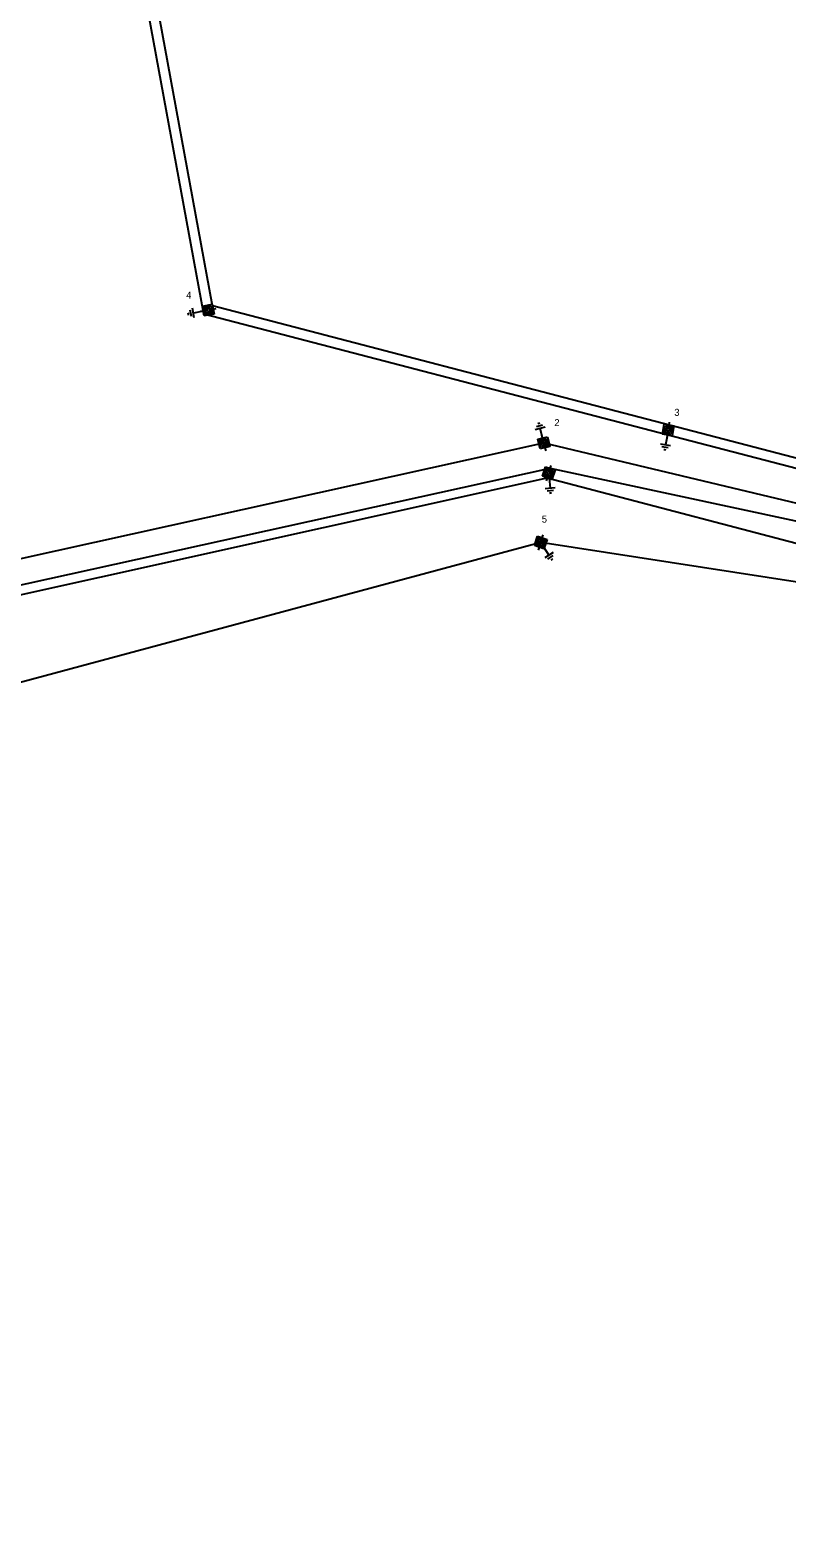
# Model space of a CAD drawing. Extents: x -763667 to -762498, y -1153000 to -1152000.
# Drawn here: x -762873.3 to -762686.7, y -1153000 to -1152628.2 of the extents above; entities that cross this region are included whole.
import ezdxf

# ---------------------------------------------------------------- set-up
doc = ezdxf.new("R2010")
doc.units = 0
for name, color, linetype in [('Vrstva 1', 7, 'Continuous'), ('Vrstva 13', 7, 'Continuous'), ('Vrstva 14', 7, 'Continuous'), ('Vrstva 15', 7, 'Continuous')]:
    doc.layers.add(name, color=color, linetype=linetype)

msp = doc.modelspace()

# ---------------------------------------------------------------- linework, layer by layer
at = {"layer": 'Vrstva 1'}
for points in [[(-762611.69, -1152755.21), (-762716.24, -1152727.97), (-762830.46, -1152698.21), (-762852.05, -1152580.65), (-762874.15, -1152462.04), (-762921.99, -1152375.79), (-763004.89, -1152226.38), (-763072.5, -1152104.65), (-763130.71, -1152000)], [(-762610.93, -1152752.83), (-762715.6, -1152725.55), (-762828.29, -1152696.16), (-762849.59, -1152580.19), (-762871.62, -1152461.96)], [(-763515.95, -1153000), (-763408.81, -1152935.67), (-763253.73, -1152842.91), (-763084.04, -1152804.87), (-762913.18, -1152766.77), (-762746.61, -1152729.95), (-762623.2, -1152759.36)], [(-763503.85, -1153000), (-763406.01, -1152941.37), (-763250.71, -1152848.67), (-763082.9, -1152811.11), (-762911.77, -1152772.97), (-762745.04, -1152736.18), (-762624.04, -1152762.13)], [(-763499.11, -1153000), (-763404.8, -1152943.47), (-763250.15, -1152850.99), (-763082.25, -1152813.42), (-762911.4, -1152775.32), (-762745.76, -1152738.55), (-762671.17, -1152758.11)], [(-762675.53, -1152765.62), (-762747.37, -1152754.51), (-762877.29, -1152789.43), (-763003.47, -1152823.28), (-763146.35, -1152861.67), (-763295.27, -1152929.58), (-763425.09, -1152988.74), (-763449.87, -1153000)]]:
    msp.add_lwpolyline(points, dxfattribs=at)
at = {"layer": 'Vrstva 13'}
for points in [[(-762830.815, -1152696.229), (-762828.403, -1152695.76)], [(-762828.403, -1152695.76), (-762827.934, -1152698.172)], [(-762830.581, -1152697.435), (-762831.315, -1152697.578)], [(-762830.346, -1152698.641), (-762830.815, -1152696.229)], [(-762830.474, -1152696.476), (-762828.665, -1152696.124)], [(-762830.122, -1152698.284), (-762830.474, -1152696.476)], [(-762827.934, -1152698.172), (-762830.346, -1152698.641)], [(-762828.314, -1152697.933), (-762830.122, -1152698.284)], [(-762830.095, -1152696.715), (-762828.889, -1152696.48)], [(-762829.861, -1152697.921), (-762830.095, -1152696.715)], [(-762828.654, -1152697.686), (-762829.861, -1152697.921)], [(-762829.697, -1152696.95), (-762829.094, -1152696.833)], [(-762829.58, -1152697.553), (-762829.697, -1152696.95)], [(-762828.977, -1152697.436), (-762829.58, -1152697.553)], [(-762829.094, -1152696.833), (-762828.977, -1152697.436)], [(-762828.889, -1152696.48), (-762828.654, -1152697.686)], [(-762828.665, -1152696.124), (-762828.314, -1152697.933)], [(-762828.169, -1152696.966), (-762827.434, -1152696.823)], [(-762717.344, -1152727.761), (-762716.917, -1152725.341)], [(-762716.917, -1152725.341), (-762714.498, -1152725.768)], [(-762715.708, -1152725.555), (-762715.578, -1152724.818)], [(-762748.098, -1152729.059), (-762745.715, -1152728.465)], [(-762747.504, -1152731.443), (-762748.098, -1152729.059)], [(-762747.721, -1152729.302), (-762745.934, -1152728.856)], [(-762747.275, -1152731.09), (-762747.721, -1152729.302)], [(-762747.354, -1152729.507), (-762746.162, -1152729.209)], [(-762746.906, -1152728.762), (-762747.087, -1152728.036)], [(-762746.162, -1152729.209), (-762745.865, -1152730.402)], [(-762745.934, -1152728.856), (-762745.488, -1152730.644)], [(-762745.715, -1152728.465), (-762745.12, -1152730.849)], [(-762714.925, -1152728.188), (-762717.344, -1152727.761)], [(-762716.992, -1152727.531), (-762716.672, -1152725.716)], [(-762715.177, -1152727.851), (-762716.992, -1152727.531)], [(-762716.672, -1152725.716), (-762714.857, -1152726.036)], [(-762716.633, -1152727.263), (-762716.419, -1152726.053)], [(-762715.423, -1152727.476), (-762716.633, -1152727.263)], [(-762716.419, -1152726.053), (-762715.21, -1152726.266)], [(-762716.27, -1152726.976), (-762716.163, -1152726.371)], [(-762715.665, -1152727.082), (-762716.27, -1152726.976)], [(-762716.134, -1152727.974), (-762716.264, -1152728.711)], [(-762716.163, -1152726.371), (-762715.559, -1152726.478)], [(-762715.559, -1152726.478), (-762715.665, -1152727.082)], [(-762715.21, -1152726.266), (-762715.423, -1152727.476)], [(-762714.857, -1152726.036), (-762715.177, -1152727.851)], [(-762714.498, -1152725.768), (-762714.925, -1152728.188)], [(-762745.12, -1152730.849), (-762747.504, -1152731.443)], [(-762747.056, -1152730.699), (-762747.354, -1152729.507)], [(-762745.488, -1152730.644), (-762747.275, -1152731.09)], [(-762745.865, -1152730.402), (-762747.056, -1152730.699)], [(-762746.991, -1152729.693), (-762746.395, -1152729.545)], [(-762746.842, -1152730.289), (-762746.991, -1152729.693)], [(-762746.246, -1152730.141), (-762746.842, -1152730.289)], [(-762746.395, -1152729.545), (-762746.246, -1152730.141)], [(-762746.312, -1152731.146), (-762746.131, -1152731.872)], [(-762746.939, -1152738.193), (-762746.18, -1152735.856)], [(-762746.558, -1152738.014), (-762745.988, -1152736.262)], [(-762746.18, -1152735.856), (-762743.843, -1152736.616)], [(-762746.165, -1152737.799), (-762745.785, -1152736.63)], [(-762745.988, -1152736.262), (-762744.236, -1152736.831)], [(-762745.785, -1152736.63), (-762744.617, -1152737.01)], [(-762745.011, -1152736.236), (-762744.78, -1152735.525)], [(-762744.236, -1152736.831), (-762744.806, -1152738.584)], [(-762743.843, -1152736.616), (-762744.603, -1152738.952)], [(-762744.603, -1152738.952), (-762746.939, -1152738.193)], [(-762744.806, -1152738.584), (-762746.558, -1152738.014)], [(-762744.997, -1152738.179), (-762746.165, -1152737.799)], [(-762745.771, -1152738.573), (-762746.002, -1152739.284)], [(-762745.766, -1152737.565), (-762745.576, -1152736.981)], [(-762745.182, -1152737.755), (-762745.766, -1152737.565)], [(-762745.576, -1152736.981), (-762744.992, -1152737.171)], [(-762744.992, -1152737.171), (-762745.182, -1152737.755)], [(-762744.617, -1152737.01), (-762744.997, -1152738.179)], [(-762748.933, -1152755.276), (-762748.133, -1152752.953)], [(-762746.61, -1152756.076), (-762748.933, -1152755.276)], [(-762748.548, -1152755.104), (-762747.949, -1152753.362)], [(-762746.806, -1152755.704), (-762748.548, -1152755.104)], [(-762748.152, -1152754.895), (-762747.752, -1152753.733)], [(-762746.991, -1152755.295), (-762748.152, -1152754.895)], [(-762748.133, -1152752.953), (-762745.81, -1152753.753)], [(-762747.949, -1152753.362), (-762746.207, -1152753.961)], [(-762747.752, -1152753.733), (-762746.591, -1152754.133)], [(-762747.749, -1152754.668), (-762747.549, -1152754.088)], [(-762747.168, -1152754.868), (-762747.749, -1152754.668)], [(-762747.549, -1152754.088), (-762746.968, -1152754.288)], [(-762746.968, -1152754.288), (-762747.168, -1152754.868)], [(-762746.591, -1152754.133), (-762746.991, -1152755.295)], [(-762746.971, -1152753.353), (-762746.728, -1152752.645)], [(-762746.207, -1152753.961), (-762746.806, -1152755.704)], [(-762745.81, -1152753.753), (-762746.61, -1152756.076)], [(-762747.771, -1152755.676), (-762748.015, -1152756.383)]]:
    msp.add_lwpolyline(points, dxfattribs=at)
at = {"layer": 'Vrstva 15'}
for points in [[(-762834.275, -1152698.157), (-762834.324, -1152697.905)], [(-762834.224, -1152698.418), (-762834.275, -1152698.157)], [(-762833.51, -1152698.79), (-762833.811, -1152697.244)], [(-762832.81, -1152699.145), (-762833.287, -1152696.691)], [(-762830.594, -1152697.441), (-762833.048, -1152697.918)], [(-762748.415, -1152725.899), (-762746.887, -1152725.518)], [(-762748.08, -1152725.167), (-762747.822, -1152725.102)], [(-762747.822, -1152725.102), (-762747.574, -1152725.04)], [(-762748.733, -1152726.618), (-762746.307, -1152726.013)], [(-762746.915, -1152728.741), (-762747.52, -1152726.315)], [(-762716.133, -1152727.989), (-762716.567, -1152730.451)], [(-762715.336, -1152730.668), (-762717.798, -1152730.234)], [(-762715.918, -1152731.195), (-762717.47, -1152730.921)], [(-762716.784, -1152731.682), (-762717.036, -1152731.637)], [(-762716.522, -1152731.728), (-762716.784, -1152731.682)], [(-762745.277, -1152738.642), (-762745.059, -1152741.133)], [(-762743.814, -1152741.024), (-762746.305, -1152741.241)], [(-762744.24, -1152741.683), (-762745.809, -1152741.821)], [(-762744.95, -1152742.378), (-762745.205, -1152742.4)], [(-762744.686, -1152742.355), (-762744.95, -1152742.378)], [(-762746.688, -1152755.554), (-762745.326, -1152757.651)], [(-762744.278, -1152756.97), (-762746.374, -1152758.331)], [(-762744.344, -1152757.753), (-762745.665, -1152758.61)], [(-762744.645, -1152758.699), (-762744.86, -1152758.838)], [(-762744.422, -1152758.554), (-762744.645, -1152758.699)]]:
    msp.add_lwpolyline(points, dxfattribs=at)

# ---------------------------------------------------------------- texts
at = {"layer": 'Vrstva 14'}
for s, p in [('4', (-762834.82, -1152694.37)), ('3', (-762714.42, -1152723.29)), ('2', (-762744.01, -1152725.82)), ('5', (-762747.11, -1152749.61))]:
    msp.add_text(s, height=1.74, dxfattribs=at).set_placement(p)

doc.saveas('drawing.dxf')
